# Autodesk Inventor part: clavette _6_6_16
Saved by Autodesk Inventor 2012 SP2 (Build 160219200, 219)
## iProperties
Created: 2013-04
Part Number: clavette _6_6_16
Material: Default
Document SubType Name: Modeling
Designer: papa
Density: 1 g/cm^3
Mass: 0.576 g
Surface Area: 4.56 cm^2
Volume: 0.576 cm^3
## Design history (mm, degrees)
node "clavette _6_6_161"
node "clavette _6_6_16"
node "Base1"
